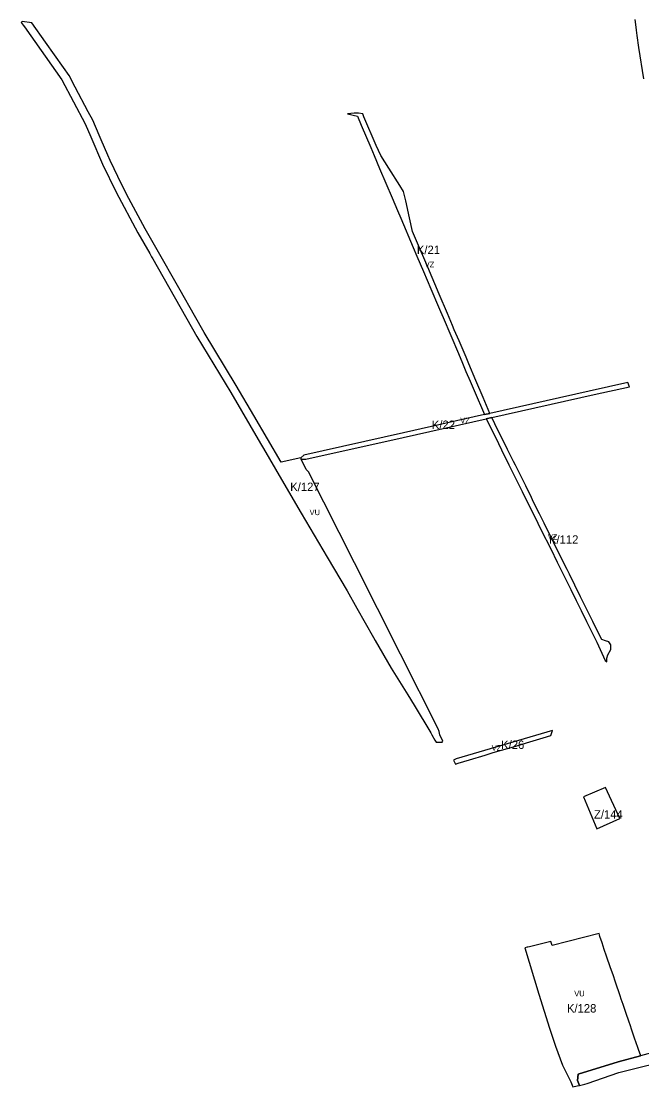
# Model space of a CAD drawing. Extents: x -521939 to -518034, y -1194984 to -1189555.
# Drawn here: x -521939 to -520833, y -1192801 to -1190901 of the extents above; entities that cross this region are included whole.
import ezdxf

# ---------------------------------------------------------------- set-up
doc = ezdxf.new("R2010")
doc.units = 0
for name, color, linetype in [('95420023', 7, 'Continuous'), ('96111023', 7, 'Continuous'), ('96141023', 7, 'Continuous'), ('96202223', 7, 'Continuous')]:
    doc.layers.add(name, color=color, linetype=linetype)

msp = doc.modelspace()

# ---------------------------------------------------------------- linework, layer by layer
at = {"layer": '95420023'}
for points in [[(-520845.07, -1190897.78), (-520843.48, -1190911.63)], [(-520843.48, -1190911.63), (-520842.9, -1190916.64)], [(-520842.9, -1190916.64), (-520841.49, -1190926.47)], [(-520841.49, -1190926.47), (-520838.45, -1190947.47)], [(-520838.45, -1190947.47), (-520829.51, -1191003.76)], [(-520897.45, -1192267.89), (-520936.99, -1192284.54)], [(-520936.99, -1192284.54), (-520912.95, -1192341.61)], [(-520872.22, -1192322.94), (-520897.45, -1192267.89)], [(-520912.95, -1192341.61), (-520872.22, -1192322.94)]]:
    msp.add_lwpolyline(points, dxfattribs=at)
at = {"layer": '96111023'}
for points in [[(-521937.86, -1190901.38), (-521939.16, -1190903.04), (-521935.96, -1190907.57)], [(-521920.24, -1190903.83), (-521937.86, -1190901.38)], [(-521935.96, -1190907.57), (-521933.74, -1190910.72)], [(-521933.74, -1190910.72), (-521866.8, -1191005.56), (-521825.27, -1191083.96)], [(-521895.95, -1190938.24), (-521920.24, -1190903.83)], [(-521864.2, -1190983.23), (-521895.95, -1190938.24)], [(-521842.92, -1191018.58), (-521853.99, -1190997.69), (-521864.2, -1190983.23)], [(-521819.76, -1191062.36), (-521842.92, -1191018.58)], [(-521811.73, -1191077.48), (-521819.76, -1191062.36)], [(-521330.04, -1191065.83), (-521337.72, -1191065.02), (-521345.44, -1191064.87), (-521357.75, -1191066.04)], [(-521357.75, -1191066.04), (-521339.87, -1191070.1)], [(-521328.5, -1191071.27), (-521330.04, -1191065.83)], [(-521825.27, -1191083.96), (-521815.35, -1191107.04)], [(-521800.42, -1191103.83), (-521811.73, -1191077.48)], [(-521339.87, -1191070.1), (-521333.03, -1191086.18)], [(-521333.03, -1191086.18), (-521316.14, -1191125.96)], [(-521306.22, -1191122.56), (-521328.5, -1191071.27)], [(-521815.35, -1191107.04), (-521794.55, -1191155.45), (-521770.21, -1191205.78), (-521731.15, -1191278.24), (-521709.89, -1191315.39)], [(-521796.68, -1191112.46), (-521800.42, -1191103.83)], [(-521785.08, -1191139.7), (-521796.68, -1191112.46)], [(-521316.14, -1191125.96), (-521309.96, -1191140.46)], [(-521298.06, -1191140.03), (-521306.22, -1191122.56)], [(-521759.83, -1191192.86), (-521780.9, -1191149.22), (-521785.08, -1191139.7)], [(-521309.96, -1191140.46), (-521300.29, -1191163.2)], [(-521291.03, -1191151.73), (-521298.06, -1191140.03)], [(-521300.29, -1191163.2), (-521277.99, -1191215.69)], [(-521283.87, -1191162.75), (-521291.03, -1191151.73)], [(-521264.02, -1191194.06), (-521283.87, -1191162.75)], [(-521747.24, -1191216.9), (-521759.83, -1191192.86)], [(-521253.66, -1191221.09), (-521257.44, -1191204.41), (-521264.02, -1191194.06)], [(-521699.07, -1191304.11), (-521718.04, -1191270.95), (-521747.24, -1191216.9)], [(-521277.99, -1191215.69), (-521268.33, -1191238.36)], [(-521247.03, -1191251.47), (-521253.66, -1191221.09)], [(-521268.33, -1191238.36), (-521262.5, -1191252.21)], [(-521262.5, -1191252.21), (-521240.42, -1191304.4)], [(-521234.63, -1191292.32), (-521241.56, -1191275.78), (-521247.03, -1191251.47)], [(-521214.55, -1191339.42), (-521234.63, -1191292.32)], [(-521709.89, -1191315.39), (-521706.74, -1191320.96)], [(-521655.79, -1191380.73), (-521699.07, -1191304.11)], [(-521240.42, -1191304.4), (-521233.83, -1191319.62)], [(-521706.74, -1191320.96), (-521704.75, -1191324.48)], [(-521704.75, -1191324.48), (-521626.26, -1191463.39)], [(-521233.83, -1191319.62), (-521222.21, -1191346.98)], [(-521222.21, -1191346.98), (-521215.47, -1191362.92)], [(-521193.95, -1191387.89), (-521214.55, -1191339.42)], [(-521215.47, -1191362.92), (-521209, -1191378.24)], [(-521630.25, -1191425.87), (-521655.79, -1191380.73)], [(-521209, -1191378.24), (-521195.36, -1191410.11)], [(-521179.31, -1191422.24), (-521193.95, -1191387.89)], [(-521195.36, -1191410.11), (-521191.65, -1191418.82)], [(-521555.8, -1191550.34), (-521613.32, -1191455.79), (-521630.25, -1191425.87)], [(-521191.65, -1191418.82), (-521187.14, -1191429.23)], [(-521187.14, -1191429.23), (-521159.78, -1191493.6)], [(-521170.39, -1191443.27), (-521179.31, -1191422.24)], [(-521167.05, -1191451.05), (-521170.39, -1191443.27)], [(-521626.26, -1191463.39), (-521565.51, -1191562.94)], [(-521158.65, -1191470.84), (-521167.05, -1191451.05)], [(-521146.18, -1191500.28), (-521158.65, -1191470.84)], [(-521159.78, -1191493.6), (-521152.49, -1191510.64)], [(-521141.21, -1191511.9), (-521146.18, -1191500.28)], [(-521152.49, -1191510.64), (-521146.31, -1191525.29)], [(-521146.31, -1191525.29), (-521138.81, -1191542.98)], [(-521128.68, -1191541.41), (-521141.21, -1191511.9)], [(-521138.81, -1191542.98), (-521131.85, -1191559.38)], [(-521115.6, -1191572.16), (-521128.68, -1191541.41)], [(-521565.51, -1191562.94), (-521512.5, -1191654.17)], [(-521524.4, -1191603.79), (-521555.8, -1191550.34)], [(-521131.85, -1191559.38), (-521113.53, -1191602.49)], [(-520857.48, -1191545.13), (-520926.4, -1191560.57), (-521103.61, -1191600.27)], [(-521100.31, -1191607.72), (-520917.76, -1191566.84), (-520854.89, -1191552.76)], [(-520854.89, -1191552.76), (-520857.48, -1191545.13)], [(-521103.61, -1191600.27), (-521115.6, -1191572.16)], [(-521103.61, -1191600.27), (-521113.53, -1191602.49)], [(-521113.53, -1191602.49), (-521103.61, -1191600.27)], [(-521440.71, -1191679.65), (-521475.77, -1191687.37), (-521524.4, -1191603.79)], [(-521113.53, -1191602.49), (-521257.76, -1191634.79), (-521435.48, -1191674.59)], [(-521258.02, -1191643.05), (-521110.35, -1191609.97)], [(-521110.35, -1191609.97), (-521100.31, -1191607.72)], [(-521100.31, -1191607.72), (-521110.35, -1191609.97)], [(-521110.35, -1191609.97), (-521094.53, -1191641.74)], [(-521094.71, -1191618.99), (-521100.31, -1191607.72)], [(-521083.44, -1191641.83), (-521094.71, -1191618.99)], [(-521512.5, -1191654.17), (-521507.47, -1191662.82)], [(-521431.76, -1191681.97), (-521258.02, -1191643.05)], [(-521094.53, -1191641.74), (-521088.54, -1191653.97)], [(-521088.54, -1191653.97), (-521082.93, -1191665.23)], [(-521075.75, -1191657.25), (-521083.44, -1191641.83)], [(-521072.03, -1191664.78), (-521075.75, -1191657.25)], [(-521507.47, -1191662.82), (-521475.16, -1191718.42)], [(-521435.48, -1191674.59), (-521440.71, -1191679.65)], [(-521082.93, -1191665.23), (-521069.59, -1191692.15)], [(-521061.5, -1191686.09), (-521072.03, -1191664.78)], [(-521440.71, -1191679.65), (-521440.4, -1191682.13)], [(-521440.4, -1191682.13), (-521440.71, -1191679.65)], [(-521440.4, -1191682.13), (-521431.76, -1191681.97)], [(-521263.12, -1192029.99), (-521345.06, -1191867.15), (-521427, -1191704.31), (-521431.33, -1191700.15), (-521440.4, -1191682.13)], [(-521069.59, -1191692.15), (-521045.95, -1191739.73)], [(-521058, -1191692.92), (-521061.5, -1191686.09)], [(-521052.87, -1191703.37), (-521058, -1191692.92)], [(-521039.79, -1191729.8), (-521052.87, -1191703.37)], [(-521475.16, -1191718.42), (-521440.41, -1191778.22), (-521394.07, -1191856.97)], [(-521029.7, -1191750.25), (-521039.79, -1191729.8)], [(-521045.95, -1191739.73), (-521033.33, -1191765.25)], [(-521025.6, -1191758.4), (-521029.7, -1191750.25)], [(-521033.33, -1191765.25), (-521024.18, -1191783.72), (-521011.95, -1191808.58)], [(-521015.3, -1191779.24), (-521025.6, -1191758.4)], [(-521006.81, -1191796.39), (-521015.3, -1191779.24)], [(-521011.95, -1191808.58), (-520995.26, -1191842.12)], [(-520989.64, -1191831.01), (-521006.81, -1191796.39)], [(-520995.26, -1191842.12), (-520983.63, -1191865.68)], [(-520981.65, -1191847.19), (-520989.64, -1191831.01)], [(-520965.82, -1191878.99), (-520981.65, -1191847.19)], [(-521394.07, -1191856.97), (-521358.15, -1191916.77), (-521340.67, -1191947.49), (-521311.39, -1192000)], [(-520983.63, -1191865.68), (-520959.52, -1191914.15)], [(-520952.13, -1191906.66), (-520961.83, -1191887.02), (-520965.82, -1191878.99)], [(-520959.52, -1191914.15), (-520949.74, -1191933.88)], [(-520941.86, -1191927.51), (-520952.13, -1191906.66)], [(-520949.74, -1191933.88), (-520941.03, -1191951.61), (-520931.19, -1191971.43)], [(-520928.16, -1191955.01), (-520941.86, -1191927.51)], [(-520919.89, -1191971.66), (-520928.16, -1191955.01)], [(-520931.19, -1191971.43), (-520921.84, -1191990.28)], [(-520912.07, -1191987.5), (-520919.89, -1191971.66)], [(-521311.39, -1192000), (-521308.38, -1192005.41)], [(-520921.84, -1191990.28), (-520912.71, -1192008.61)], [(-520897.64, -1192005.71), (-520904.09, -1192003.54), (-520912.07, -1191987.5)], [(-521308.38, -1192005.41), (-521279.68, -1192054.79), (-521250, -1192102.48)], [(-520912.71, -1192008.61), (-520898.22, -1192040.98)], [(-520895.08, -1192040.13), (-520895.06, -1192036.66), (-520893.18, -1192030.83), (-520888.16, -1192021.2), (-520888.12, -1192013.43), (-520891.41, -1192007.81), (-520897.64, -1192005.71)], [(-521193.86, -1192167.63), (-521196.15, -1192163.08), (-521263.12, -1192029.99)], [(-520898.22, -1192040.98), (-520895.11, -1192043.42)], [(-520895.11, -1192043.42), (-520895.08, -1192040.13)], [(-521250, -1192102.48), (-521238.5, -1192120.96), (-521209.18, -1192170.31)], [(-521209.18, -1192170.31), (-521207.02, -1192173.96)], [(-521193.11, -1192173.56), (-521193.86, -1192167.63)], [(-520992.3, -1192166.01), (-521163.51, -1192216.7)], [(-520994.96, -1192175.05), (-520992.3, -1192166.01)], [(-521207.02, -1192173.96), (-521201.6, -1192183.07)], [(-521201.6, -1192183.07), (-521199.33, -1192186.9)], [(-521199.33, -1192186.9), (-521188.6, -1192186.94), (-521187.37, -1192184.96)], [(-521187.37, -1192184.96), (-521193.11, -1192173.56)], [(-521057.45, -1192193.65), (-521038.14, -1192187.92)], [(-521038.14, -1192187.92), (-521020.52, -1192182.75)], [(-521020.52, -1192182.75), (-521008.84, -1192179.25)], [(-521008.84, -1192179.25), (-520994.96, -1192175.05)], [(-521111.98, -1192209.79), (-521097.8, -1192205.47)], [(-521097.8, -1192205.47), (-521072.45, -1192198.08)], [(-521072.45, -1192198.08), (-521057.45, -1192193.65)], [(-521163.51, -1192216.7), (-521168.5, -1192218.83)], [(-521168.5, -1192218.83), (-521164.96, -1192226.12)], [(-521164.96, -1192226.12), (-521160.1, -1192224.03)], [(-521160.1, -1192224.03), (-521140.15, -1192218.12)], [(-521140.15, -1192218.12), (-521111.98, -1192209.79)], [(-520908.99, -1192527.86), (-520992.77, -1192549.69)], [(-520903.57, -1192544.89), (-520907.44, -1192533.58), (-520908.21, -1192530.72), (-520908.99, -1192527.86)], [(-521033.12, -1192551.66), (-521036.09, -1192552.43), (-521037.14, -1192552.7)], [(-521030.87, -1192551.11), (-521033.12, -1192551.66)], [(-520995.13, -1192542.04), (-521030.87, -1192551.11)], [(-520992.77, -1192549.69), (-520995.13, -1192542.04)], [(-520899.67, -1192556.33), (-520903.57, -1192544.89)], [(-521037.14, -1192552.7), (-521041.32, -1192553.76)], [(-521041.32, -1192553.76), (-521016.55, -1192636.53)], [(-520895.43, -1192568.72), (-520899.67, -1192556.33)], [(-520888.34, -1192589.46), (-520895.43, -1192568.72)], [(-520884.03, -1192602.07), (-520888.34, -1192589.46)], [(-520879.59, -1192615.06), (-520884.03, -1192602.07)], [(-520871.37, -1192639.12), (-520879.59, -1192615.06)], [(-521016.55, -1192636.53), (-520997.18, -1192696.65)], [(-520869.28, -1192645.23), (-520871.37, -1192639.12)], [(-520866, -1192654.84), (-520869.28, -1192645.23)], [(-520861.2, -1192668.88), (-520866, -1192654.84)], [(-520855.19, -1192686.47), (-520861.2, -1192668.88)], [(-520997.18, -1192696.65), (-520986.7, -1192729.16), (-520974.15, -1192762.68), (-520959.24, -1192792.44)], [(-520853.74, -1192690.71), (-520855.19, -1192686.47)], [(-520850.47, -1192700.26), (-520853.74, -1192690.71)], [(-520846.21, -1192712.75), (-520850.47, -1192700.26)], [(-520596.04, -1192695.13), (-520758.3, -1192728.9), (-520815.45, -1192740.8), (-520834.88, -1192746.05)], [(-520842.13, -1192724.66), (-520846.21, -1192712.75)], [(-520840.49, -1192729.47), (-520842.13, -1192724.66)], [(-520837.96, -1192736.86), (-520840.49, -1192729.47)], [(-520834.88, -1192746.05), (-520835.3, -1192744.66), (-520837.96, -1192736.86)], [(-520946.38, -1192779.22), (-520874.84, -1192756.86), (-520834.88, -1192746.05)], [(-520874.84, -1192756.86), (-520946.38, -1192779.22)], [(-520930.47, -1192795.56), (-520873.66, -1192776.25), (-520770.76, -1192750.7)], [(-520834.88, -1192746.05), (-520874.84, -1192756.86)], [(-520946.38, -1192779.22), (-520947.19, -1192790.27)], [(-520947.19, -1192790.27), (-520946.38, -1192779.22)], [(-520959.24, -1192792.44), (-520955.72, -1192801.31)], [(-520947.19, -1192790.27), (-520944.08, -1192798.91)], [(-520944.08, -1192798.91), (-520947.19, -1192790.27)], [(-520944.08, -1192798.91), (-520934.56, -1192796.95), (-520930.47, -1192795.56)], [(-520955.72, -1192801.31), (-520948.03, -1192799.73)], [(-520948.03, -1192799.73), (-520944.08, -1192798.91)]]:
    msp.add_lwpolyline(points, dxfattribs=at)
at = {"layer": '96141023'}
for points in [[(-521937.86, -1190901.38), (-521939.16, -1190903.04), (-521935.96, -1190907.57)], [(-521920.24, -1190903.83), (-521937.86, -1190901.38)], [(-521935.96, -1190907.57), (-521933.74, -1190910.72)], [(-521933.74, -1190910.72), (-521866.8, -1191005.56), (-521825.27, -1191083.96)], [(-521895.95, -1190938.24), (-521920.24, -1190903.83)], [(-521864.2, -1190983.23), (-521895.95, -1190938.24)], [(-521842.92, -1191018.58), (-521853.99, -1190997.69), (-521864.2, -1190983.23)], [(-521819.76, -1191062.36), (-521842.92, -1191018.58)], [(-521811.73, -1191077.48), (-521819.76, -1191062.36)], [(-521825.27, -1191083.96), (-521815.35, -1191107.04)], [(-521800.42, -1191103.83), (-521811.73, -1191077.48)], [(-521815.35, -1191107.04), (-521794.55, -1191155.45), (-521770.21, -1191205.78), (-521731.15, -1191278.24), (-521709.89, -1191315.39)], [(-521796.68, -1191112.46), (-521800.42, -1191103.83)], [(-521785.08, -1191139.7), (-521796.68, -1191112.46)], [(-521759.83, -1191192.86), (-521780.9, -1191149.22), (-521785.08, -1191139.7)], [(-521747.24, -1191216.9), (-521759.83, -1191192.86)], [(-521699.07, -1191304.11), (-521718.04, -1191270.95), (-521747.24, -1191216.9)], [(-521709.89, -1191315.39), (-521706.74, -1191320.96)], [(-521655.79, -1191380.73), (-521699.07, -1191304.11)], [(-521706.74, -1191320.96), (-521704.75, -1191324.48)], [(-521704.75, -1191324.48), (-521626.26, -1191463.39)], [(-521630.25, -1191425.87), (-521655.79, -1191380.73)], [(-521555.8, -1191550.34), (-521613.32, -1191455.79), (-521630.25, -1191425.87)], [(-521626.26, -1191463.39), (-521565.51, -1191562.94)], [(-521565.51, -1191562.94), (-521512.5, -1191654.17)], [(-521524.4, -1191603.79), (-521555.8, -1191550.34)], [(-521440.71, -1191679.65), (-521475.77, -1191687.37), (-521524.4, -1191603.79)], [(-521512.5, -1191654.17), (-521507.47, -1191662.82)], [(-521507.47, -1191662.82), (-521475.16, -1191718.42)], [(-521440.4, -1191682.13), (-521440.71, -1191679.65)], [(-521263.12, -1192029.99), (-521345.06, -1191867.15), (-521427, -1191704.31), (-521431.33, -1191700.15), (-521440.4, -1191682.13)], [(-521475.16, -1191718.42), (-521440.41, -1191778.22), (-521394.07, -1191856.97)], [(-521394.07, -1191856.97), (-521358.15, -1191916.77), (-521340.67, -1191947.49), (-521311.39, -1192000)], [(-521311.39, -1192000), (-521308.38, -1192005.41)], [(-521308.38, -1192005.41), (-521279.68, -1192054.79), (-521250, -1192102.48)], [(-521193.86, -1192167.63), (-521196.15, -1192163.08), (-521263.12, -1192029.99)], [(-521250, -1192102.48), (-521238.5, -1192120.96), (-521209.18, -1192170.31)], [(-521209.18, -1192170.31), (-521207.02, -1192173.96)], [(-521193.11, -1192173.56), (-521193.86, -1192167.63)], [(-521207.02, -1192173.96), (-521201.6, -1192183.07)], [(-521201.6, -1192183.07), (-521199.33, -1192186.9)], [(-521199.33, -1192186.9), (-521188.6, -1192186.94), (-521187.37, -1192184.96)], [(-521187.37, -1192184.96), (-521193.11, -1192173.56)], [(-520908.99, -1192527.86), (-520992.77, -1192549.69)], [(-520903.57, -1192544.89), (-520907.44, -1192533.58), (-520908.21, -1192530.72), (-520908.99, -1192527.86)], [(-521033.12, -1192551.66), (-521036.09, -1192552.43), (-521037.14, -1192552.7)], [(-521030.87, -1192551.11), (-521033.12, -1192551.66)], [(-520995.13, -1192542.04), (-521030.87, -1192551.11)], [(-520992.77, -1192549.69), (-520995.13, -1192542.04)], [(-520899.67, -1192556.33), (-520903.57, -1192544.89)], [(-521037.14, -1192552.7), (-521041.32, -1192553.76)], [(-521041.32, -1192553.76), (-521016.55, -1192636.53)], [(-520895.43, -1192568.72), (-520899.67, -1192556.33)], [(-520888.34, -1192589.46), (-520895.43, -1192568.72)], [(-520884.03, -1192602.07), (-520888.34, -1192589.46)], [(-520879.59, -1192615.06), (-520884.03, -1192602.07)], [(-520871.37, -1192639.12), (-520879.59, -1192615.06)], [(-521016.55, -1192636.53), (-520997.18, -1192696.65)], [(-520869.28, -1192645.23), (-520871.37, -1192639.12)], [(-520866, -1192654.84), (-520869.28, -1192645.23)], [(-520861.2, -1192668.88), (-520866, -1192654.84)], [(-520855.19, -1192686.47), (-520861.2, -1192668.88)], [(-520997.18, -1192696.65), (-520986.7, -1192729.16), (-520974.15, -1192762.68), (-520959.24, -1192792.44)], [(-520853.74, -1192690.71), (-520855.19, -1192686.47)], [(-520850.47, -1192700.26), (-520853.74, -1192690.71)], [(-520846.21, -1192712.75), (-520850.47, -1192700.26)], [(-520596.04, -1192695.13), (-520758.3, -1192728.9), (-520815.45, -1192740.8), (-520834.88, -1192746.05)], [(-520842.13, -1192724.66), (-520846.21, -1192712.75)], [(-520840.49, -1192729.47), (-520842.13, -1192724.66)], [(-520837.96, -1192736.86), (-520840.49, -1192729.47)], [(-520834.88, -1192746.05), (-520835.3, -1192744.66), (-520837.96, -1192736.86)], [(-520946.38, -1192779.22), (-520874.84, -1192756.86)], [(-520874.84, -1192756.86), (-520946.38, -1192779.22)], [(-520930.47, -1192795.56), (-520873.66, -1192776.25), (-520770.76, -1192750.7)], [(-520874.84, -1192756.86), (-520834.88, -1192746.05)], [(-520834.88, -1192746.05), (-520874.84, -1192756.86)], [(-520947.19, -1192790.27), (-520946.38, -1192779.22)], [(-520946.38, -1192779.22), (-520947.19, -1192790.27)], [(-520959.24, -1192792.44), (-520955.72, -1192801.31)], [(-520944.08, -1192798.91), (-520947.19, -1192790.27)], [(-520947.19, -1192790.27), (-520944.08, -1192798.91)], [(-520944.08, -1192798.91), (-520934.56, -1192796.95), (-520930.47, -1192795.56)], [(-520955.72, -1192801.31), (-520948.03, -1192799.73)], [(-520948.03, -1192799.73), (-520944.08, -1192798.91)]]:
    msp.add_lwpolyline(points, dxfattribs=at)
at = {"layer": '96202223'}
for points in [[(-521330.04, -1191065.83), (-521337.72, -1191065.02), (-521345.44, -1191064.87), (-521357.75, -1191066.04)], [(-521357.75, -1191066.04), (-521339.87, -1191070.1)], [(-521328.5, -1191071.27), (-521330.04, -1191065.83)], [(-521339.87, -1191070.1), (-521333.03, -1191086.18)], [(-521333.03, -1191086.18), (-521316.14, -1191125.96)], [(-521306.22, -1191122.56), (-521328.5, -1191071.27)], [(-521316.14, -1191125.96), (-521309.96, -1191140.46)], [(-521298.06, -1191140.03), (-521306.22, -1191122.56)], [(-521309.96, -1191140.46), (-521300.29, -1191163.2)], [(-521291.03, -1191151.73), (-521298.06, -1191140.03)], [(-521300.29, -1191163.2), (-521277.99, -1191215.69)], [(-521283.87, -1191162.75), (-521291.03, -1191151.73)], [(-521264.02, -1191194.06), (-521283.87, -1191162.75)], [(-521253.66, -1191221.09), (-521257.44, -1191204.41), (-521264.02, -1191194.06)], [(-521277.99, -1191215.69), (-521268.33, -1191238.36)], [(-521247.03, -1191251.47), (-521253.66, -1191221.09)], [(-521268.33, -1191238.36), (-521262.5, -1191252.21)], [(-521262.5, -1191252.21), (-521240.42, -1191304.4)], [(-521234.63, -1191292.32), (-521241.56, -1191275.78), (-521247.03, -1191251.47)], [(-521214.55, -1191339.42), (-521234.63, -1191292.32)], [(-521240.42, -1191304.4), (-521233.83, -1191319.62)], [(-521233.83, -1191319.62), (-521222.21, -1191346.98)], [(-521222.21, -1191346.98), (-521215.47, -1191362.92)], [(-521193.95, -1191387.89), (-521214.55, -1191339.42)], [(-521215.47, -1191362.92), (-521209, -1191378.24)], [(-521209, -1191378.24), (-521195.36, -1191410.11)], [(-521179.31, -1191422.24), (-521193.95, -1191387.89)], [(-521195.36, -1191410.11), (-521191.65, -1191418.82)], [(-521191.65, -1191418.82), (-521187.14, -1191429.23)], [(-521187.14, -1191429.23), (-521159.78, -1191493.6)], [(-521170.39, -1191443.27), (-521179.31, -1191422.24)], [(-521167.05, -1191451.05), (-521170.39, -1191443.27)], [(-521158.65, -1191470.84), (-521167.05, -1191451.05)], [(-521146.18, -1191500.28), (-521158.65, -1191470.84)], [(-521159.78, -1191493.6), (-521152.49, -1191510.64)], [(-521141.21, -1191511.9), (-521146.18, -1191500.28)], [(-521152.49, -1191510.64), (-521146.31, -1191525.29)], [(-521146.31, -1191525.29), (-521138.81, -1191542.98)], [(-521128.68, -1191541.41), (-521141.21, -1191511.9)], [(-521138.81, -1191542.98), (-521131.85, -1191559.38)], [(-521115.6, -1191572.16), (-521128.68, -1191541.41)], [(-521131.85, -1191559.38), (-521113.53, -1191602.49)], [(-520857.48, -1191545.13), (-520926.4, -1191560.57), (-521103.61, -1191600.27)], [(-521100.31, -1191607.72), (-520917.76, -1191566.84), (-520854.89, -1191552.76)], [(-520854.89, -1191552.76), (-520857.48, -1191545.13)], [(-521103.61, -1191600.27), (-521115.6, -1191572.16)], [(-521103.61, -1191600.27), (-521113.53, -1191602.49)], [(-521113.53, -1191602.49), (-521103.61, -1191600.27)], [(-521113.53, -1191602.49), (-521257.76, -1191634.79), (-521435.48, -1191674.59)], [(-521258.02, -1191643.05), (-521110.35, -1191609.97)], [(-521110.35, -1191609.97), (-521100.31, -1191607.72)], [(-521100.31, -1191607.72), (-521110.35, -1191609.97)], [(-521110.35, -1191609.97), (-521094.53, -1191641.74)], [(-521094.71, -1191618.99), (-521100.31, -1191607.72)], [(-521083.44, -1191641.83), (-521094.71, -1191618.99)], [(-521431.76, -1191681.97), (-521258.02, -1191643.05)], [(-521094.53, -1191641.74), (-521088.54, -1191653.97)], [(-521088.54, -1191653.97), (-521082.93, -1191665.23)], [(-521075.75, -1191657.25), (-521083.44, -1191641.83)], [(-521072.03, -1191664.78), (-521075.75, -1191657.25)], [(-521435.48, -1191674.59), (-521440.71, -1191679.65)], [(-521082.93, -1191665.23), (-521069.59, -1191692.15)], [(-521061.5, -1191686.09), (-521072.03, -1191664.78)], [(-521440.71, -1191679.65), (-521440.4, -1191682.13)], [(-521440.4, -1191682.13), (-521431.76, -1191681.97)], [(-521069.59, -1191692.15), (-521045.95, -1191739.73)], [(-521058, -1191692.92), (-521061.5, -1191686.09)], [(-521052.87, -1191703.37), (-521058, -1191692.92)], [(-521039.79, -1191729.8), (-521052.87, -1191703.37)], [(-521029.7, -1191750.25), (-521039.79, -1191729.8)], [(-521045.95, -1191739.73), (-521033.33, -1191765.25)], [(-521025.6, -1191758.4), (-521029.7, -1191750.25)], [(-521033.33, -1191765.25), (-521024.18, -1191783.72), (-521011.95, -1191808.58)], [(-521015.3, -1191779.24), (-521025.6, -1191758.4)], [(-521006.81, -1191796.39), (-521015.3, -1191779.24)], [(-521011.95, -1191808.58), (-520995.26, -1191842.12)], [(-520989.64, -1191831.01), (-521006.81, -1191796.39)], [(-520995.26, -1191842.12), (-520983.63, -1191865.68)], [(-520981.65, -1191847.19), (-520989.64, -1191831.01)], [(-520965.82, -1191878.99), (-520981.65, -1191847.19)], [(-520983.63, -1191865.68), (-520959.52, -1191914.15)], [(-520952.13, -1191906.66), (-520961.83, -1191887.02), (-520965.82, -1191878.99)], [(-520959.52, -1191914.15), (-520949.74, -1191933.88)], [(-520941.86, -1191927.51), (-520952.13, -1191906.66)], [(-520949.74, -1191933.88), (-520941.03, -1191951.61), (-520931.19, -1191971.43)], [(-520928.16, -1191955.01), (-520941.86, -1191927.51)], [(-520919.89, -1191971.66), (-520928.16, -1191955.01)], [(-520931.19, -1191971.43), (-520921.84, -1191990.28)], [(-520912.07, -1191987.5), (-520919.89, -1191971.66)], [(-520921.84, -1191990.28), (-520912.71, -1192008.61)], [(-520897.64, -1192005.71), (-520904.09, -1192003.54), (-520912.07, -1191987.5)], [(-520912.71, -1192008.61), (-520898.22, -1192040.98)], [(-520895.08, -1192040.13), (-520895.06, -1192036.66), (-520893.18, -1192030.83), (-520888.16, -1192021.2), (-520888.12, -1192013.43), (-520891.41, -1192007.81), (-520897.64, -1192005.71)], [(-520898.22, -1192040.98), (-520895.11, -1192043.42)], [(-520895.11, -1192043.42), (-520895.08, -1192040.13)], [(-520992.3, -1192166.01), (-521163.51, -1192216.7)], [(-520994.96, -1192175.05), (-520992.3, -1192166.01)], [(-521057.45, -1192193.65), (-521038.14, -1192187.92)], [(-521038.14, -1192187.92), (-521020.52, -1192182.75)], [(-521020.52, -1192182.75), (-521008.84, -1192179.25)], [(-521008.84, -1192179.25), (-520994.96, -1192175.05)], [(-521111.98, -1192209.79), (-521097.8, -1192205.47)], [(-521097.8, -1192205.47), (-521072.45, -1192198.08)], [(-521072.45, -1192198.08), (-521057.45, -1192193.65)], [(-521163.51, -1192216.7), (-521168.5, -1192218.83)], [(-521168.5, -1192218.83), (-521164.96, -1192226.12)], [(-521164.96, -1192226.12), (-521160.1, -1192224.03)], [(-521160.1, -1192224.03), (-521140.15, -1192218.12)], [(-521140.15, -1192218.12), (-521111.98, -1192209.79)]]:
    msp.add_lwpolyline(points, dxfattribs=at)

# ---------------------------------------------------------------- texts
at = {"layer": '95420023'}
msp.add_text('Z/144', height=15, rotation=360, dxfattribs=at).set_placement((-520918.01, -1192323.06))
at = {"layer": '96111023'}
for s, rotation, p in [('K/21', 0, (-521233.85, -1191316.12)), ('K/22', 360, (-521207.13, -1191628.08)), ('K/127', 0, (-521459.66, -1191738.84)), ('K/112', 0, (-520998.28, -1191832.82)), ('K/26', 0, (-521083.57, -1192198.83)), ('K/128', 0, (-520966.23, -1192669.01))]:
    msp.add_text(s, height=15, rotation=rotation, dxfattribs=at).set_placement(p)
at = {"layer": '96141023'}
for rotation, p in [(360, (-521425.15, -1191781.78)), (0, (-520953.25, -1192640.23))]:
    msp.add_text('VU', height=10, rotation=rotation, dxfattribs=at).set_placement(p)
at = {"layer": '96202223'}
for rotation, p in [(0, (-521219.96, -1191339.85)), (0, (-521156.44, -1191617.8)), (360, (-521000.25, -1191825.86)), (360, (-521100.5, -1192201.98))]:
    msp.add_text('VZ', height=10, rotation=rotation, dxfattribs=at).set_placement(p)

doc.saveas('drawing.dxf')
